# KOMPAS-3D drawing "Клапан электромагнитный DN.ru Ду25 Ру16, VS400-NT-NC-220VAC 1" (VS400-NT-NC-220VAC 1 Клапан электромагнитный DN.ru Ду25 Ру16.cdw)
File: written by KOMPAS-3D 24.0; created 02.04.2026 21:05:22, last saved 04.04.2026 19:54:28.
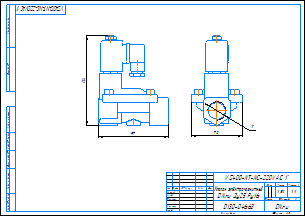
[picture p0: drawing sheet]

Document properties: c3d_UniqueCompID: ef56311e-7521-43dc-8291-0e6108b3d81d; Обозначение: VS400-ET-NC-220VAC 1; Наименование: Клапан электромагнитный DN.ru Ду25 Ру16; Автор: artio; Класс точности: c; Знак неуказанной шероховатости: Шероховатость не задана; Рассекать на разрезах: Да; c3d_UniqueCompID: ef56311e-7521-43dc-8291-0e6108b3d81d; Обозначение: VS400-ET-NC-220VAC 1-2; Наименование: Клапан электромагнитный DN.ru Ду15 Ру16; Автор: artio; Класс точности: c; Знак неуказанной шероховатости: Шероховатость не задана; Рассекать на разрезах: Да; c3d_UniqueCompID: ef56311e-7521-43dc-8291-0e6108b3d81d; Обозначение: VS400-ET-NC-220VAC 3-4; Наименование: Клапан электромагнитный DN.ru Ду20 Ру16; Автор: artio; Класс точности: c; Знак неуказанной шероховатости: Шероховатость не задана; Рассекать на разрезах: Да; c3d_UniqueCompID: ef56311e-7521-43dc-8291-0e6108b3d81d; Обозначение: VS400-ET-NC-220VAC 3-8; Наименование: Клапан электромагнитный DN.ru Ду10 Ру16; Автор: artio; Класс точности: c; Знак неуказанной шероховатости: Шероховатость не задана; Рассекать на разрезах: Да; Автор: artio; Форматы листов документа: A3; Полное имя файла: VS400-NT-NC-220VAC 1 Клапан электромагнитный DN.ru Ду25 Ру16.m3d; Масса: 1.524; Наименование: Клапан электромагнитный DN.ru Ду25 Ру16; Количество листов документа: 1; Примечание: D130-04663

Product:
- Body: Тело 1  | qty 1
    Масса: 1.76797
- Part/product: Клапан электромагнитный DN.ru Ду25 Ру16  | designation VS400-NT-NC-220VAC 1
    Масса: 1.524
    Раздел спецификации: Прочие изделия
    Примечание: D130-04663
    additional columns: ef56311e-7521-43dc-8291-0e6108b3d81d; VS400-ET-NC-220VAC 1; artio; c; Шероховатость не задана; Да

Views: Вид 1, Спереди, Проекционный вид 2
Referenced files in C:\Users\artio\OneDrive\Рабочий стол\Клапан электромагнитный DN.ru VS4x-xT-NC-x\DN10\: VS400-ET-NC-220VAC 3-8 Клапан электромагнитный DN.ru Ду10 Ру16.m3d, VS400-ET-NC-220VAC 3-8 Клапан электромагнитный DN.ru Ду10 Ру16.cdw
Referenced files in C:\Users\artio\OneDrive\Рабочий стол\Клапан электромагнитный DN.ru\VS400-NT-NC\VS400-NT-NC-220VAC\: VS400-NT-NC-220VAC 1 Клапан электромагнитный DN.ru Ду25 Ру16.m3d
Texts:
  VS400-NT-NC-220VAC 1
  Линейный размер
  Клапан электромагнитный
  DN.ru Ду25 Ру16
  VS400-NT-NC-220VAC 1"
  VS400-NT-NC-220VAC 1"-
  Клапан электромагнитный DN.ru Ду25 Ру16
  VS400-NT-NC-220VAC 1 Клапан электромагнитный DN.ru Ду25 Ру16
Dimensions and other numbers on the sheet: 0; 3; 2; 4; 70; 97; 124; 1:1; 1; 1,52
